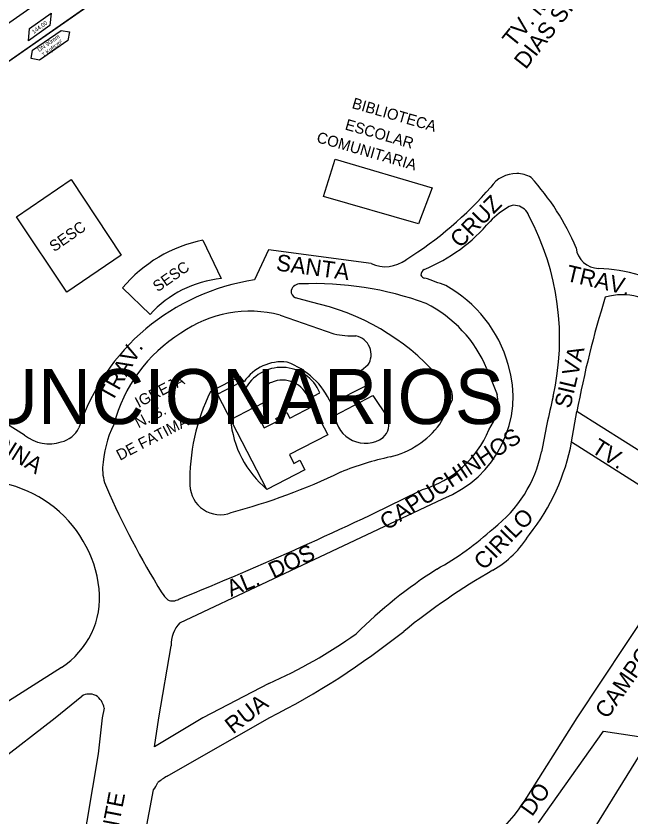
# Model space of a CAD drawing. Extents: x 325709 to 364434, y 7573432 to 7597073.
# Drawn here: x 337753.4 to 337977, y 7589465.9 to 7589757.3 of the extents above; entities that cross this region are included whole.
import ezdxf

# ---------------------------------------------------------------- set-up
doc = ezdxf.new("R2010")
doc.units = 0
for name, color, linetype in [('EDIFEXISTENT', 7, 'Continuous'), ('EDIFIDENTIF', 7, 'Continuous'), ('EDIFOBRAEXIS', 7, 'Continuous'), ('LIMITE_BAIRROS_MUNICIPIOS', 7, 'Continuous'), ('LOGRADOURO', 7, 'Continuous'), ('LOGRADOURO_TEXTO', 7, 'Continuous'), ('SIMBOLO', 7, 'Continuous'), ('TEXTO', 7, 'Continuous'), ('TUBO_PEAD_GN_90', 7, 'Continuous')]:
    doc.layers.add(name, color=color, linetype=linetype)

msp = doc.modelspace()

# ---------------------------------------------------------------- linework, layer by layer
at = {"layer": 'EDIFEXISTENT'}
for p, q in [((337865.22, 7589691.61), (337869.48, 7589705.19)), ((337869.48, 7589705.19), (337904.68, 7589694.73)), ((337753.58, 7589684.27), (337773.5, 7589697.83)), ((337773.5, 7589697.83), (337791.63, 7589670.29)), ((337904.68, 7589694.73), (337899.77, 7589681.63)), ((337899.77, 7589681.63), (337865.22, 7589691.61)), ((337771.86, 7589656.78), (337753.58, 7589684.27)), ((337821.38, 7589675.69), (337828.01, 7589661.75)), ((337791.63, 7589670.29), (337771.86, 7589656.78)), ((337802.14, 7589648.71), (337792.16, 7589658.35)), ((337826.65, 7589619.68), (337834.98, 7589624.01)), ((337834.98, 7589624.01), (337839.78, 7589614.76)), ((337859.74, 7589618.02), (337863.92, 7589620.19)), ((337844.63, 7589585.05), (337826.65, 7589619.68)), ((337839.78, 7589614.76), (337831.4, 7589610.41)), ((337839.78, 7589614.76), (337843.97, 7589616.93)), ((337839.78, 7589614.76), (337843.6, 7589607.39)), ((337852.96, 7589610.95), (337861.4, 7589615.33)), ((337861.4, 7589615.33), (337866.79, 7589604.93)), ((337847.94, 7589610.89), (337851.92, 7589612.96)), ((337851.92, 7589612.96), (337852.96, 7589610.95)), ((337843.6, 7589607.39), (337848.45, 7589609.91)), ((337848.45, 7589609.91), (337847.94, 7589610.89)), ((337866.79, 7589604.93), (337852.81, 7589597.68)), ((337852.81, 7589597.68), (337854.46, 7589594.51)), ((337854.46, 7589594.51), (337856.65, 7589595.65)), ((337856.65, 7589595.65), (337858.46, 7589592.17)), ((337858.46, 7589592.17), (337844.63, 7589585.05))]:
    msp.add_line(p, q, dxfattribs=at)
for centre, radius, start, end in [((337831.24, 7589625.78), 50.87, 101.1753, 140.1958), ((337832.18, 7589621.28), 40.68, 95.8819, 137.6058), ((337849.99, 7589614.35), 15.09, 22.7351, 152.9065), ((337848.02, 7589619.5), 4.79, 110.2139, 212.3529), ((337850.32, 7589614.89), 9.93, 18.3749, 113.5191)]:
    msp.add_arc(centre, radius, start, end, dxfattribs=at)
at = {"layer": 'EDIFOBRAEXIS'}
for p, q in [((337860.89, 7589653.12), (337855.01, 7589654.71)), ((337869.39, 7589611.91), (337883.17, 7589619.21)), ((337883.17, 7589619.21), (337888.63, 7589611.08))]:
    msp.add_line(p, q, dxfattribs=at)
msp.add_lwpolyline([(337836.34, 7589624.22), (337834.89, 7589626.07), (337824.09, 7589620.61)], dxfattribs=at)
for centre, radius, start, end in [((337856, 7589657.06), 2.54, 171.2027, 247.0167), ((337842.87, 7589569.44), 85.6, 41.776, 77.8491), ((337850.09, 7589614.83), 16.65, 83.4955, 145.648), ((337841.97, 7589604.66), 28.51, 23.989, 69.4661), ((337903.29, 7589618.24), 8.91, 357.0377, 67.4592), ((337889.76, 7589588.41), 73.14, 153.8787, 181.4576), ((337775.16, 7589683.17), 151.83, 330.6463, 334.4887), ((337880.43, 7589612.91), 11.09, 185.1891, 305.4939), ((337868.86, 7589613.82), 37.61, 185.1982, 229.8969), ((337882.53, 7589608.77), 6.52, 311.6203, 20.8159), ((337882.25, 7589627.45), 31.42, 283.2689, 323.4734), ((337913.15, 7589487.48), 111.92, 102.2204, 111.8395), ((337770.87, 7589801.87), 233.32, 285.1026, 295.5529), ((337827.64, 7589586.84), 11, 181.5218, 291.4631)]:
    msp.add_arc(centre, radius, start, end, dxfattribs=at)
at = {"layer": 'LIMITE_BAIRROS_MUNICIPIOS'}
msp.add_lwpolyline([(337471.68, 7589702.11), (337850.59, 7589885.17), (338105.97, 7589691.77), (337839.73, 7589261.51)], dxfattribs=at)
at = {"layer": 'LOGRADOURO'}
for p, q in [((337777.7, 7589773.53), (337681.39, 7589706.29)), ((337756.51, 7589604.8), (337681.39, 7589651.86)), ((337849.42, 7589648.46), (337869.03, 7589641.59)), ((337924.66, 7589628.94), (337928.42, 7589619.62)), ((337955.46, 7589602.34), (337957.37, 7589613.36)), ((337986.4, 7589595.08), (337957.37, 7589613.36)), ((337955.46, 7589602.34), (338003.49, 7589571.67)), ((337812.94, 7589536.51), (337908.56, 7589581.66)), ((338003.49, 7589571.67), (337957.37, 7589501.91)), ((337805.35, 7589501.91), (337809.76, 7589528.15)), ((337769.92, 7589520.28), (337741.14, 7589501.91)), ((337845.36, 7589514.39), (337821.3, 7589501.91)), ((337767.58, 7589501.91), (337777.32, 7589509.85)), ((337785.44, 7589505.39), (337784.7, 7589501.91)), ((337723.81, 7589467.93), (337767.58, 7589501.91)), ((337821.3, 7589501.91), (337803.75, 7589491.32)), ((337803.75, 7589491.32), (337805.35, 7589501.91)), ((337808.33, 7589480.67), (337845.48, 7589501.91)), ((337957.37, 7589501.91), (337937.57, 7589470.65)), ((337943.46, 7589463.74), (337967.01, 7589497.08)), ((337967.01, 7589497.08), (338018.98, 7589489.01)), ((337789.48, 7589402.84), (337803.39, 7589475.72))]:
    msp.add_line(p, q, dxfattribs=at)
for points in [[(337685.23, 7589695.1), (337851.99, 7589811.81), (337884.5, 7589834.2)], [(337882.51, 7589667.18), (337845.21, 7589672.2), (337840.14, 7589661.24)], [(337881.39, 7589630.23), (337879.07, 7589628.26), (337881.02, 7589622.84), (337868.02, 7589616.26)], [(337784.7, 7589501.91), (337783.28, 7589488.81), (337768.69, 7589402.37)]]:
    msp.add_lwpolyline(points, dxfattribs=at)
for centre, radius, start, end in [((337935.34, 7589688.88), 11.08, 89.0512, 146.266), ((337935.34, 7589688.88), 11.08, 61.0979, 89.0512), ((337873.38, 7589637.56), 90.86, 22.891, 42.1924), ((337821.26, 7589786.42), 139.09, 302.1242, 318.9295), ((337949.88, 7589658.82), 33.83, 120.451, 135.4175), ((337934.56, 7589684.39), 4.03, 72.6768, 116.9118), ((337934.71, 7589682.85), 5.48, 18.6993, 78.972), ((337856.47, 7589639.98), 94.62, 347.0801, 28.1464), ((337877.72, 7589723.12), 62.89, 292.5737, 319.8465), ((337965.52, 7589673.9), 8.49, 186.7436, 268.1865), ((337887.65, 7589678.58), 12.51, 245.7455, 307.2705), ((337903.27, 7589662.81), 2.64, 122.206, 175.7575), ((337963.92, 7589610.47), 54.96, 72.8158, 88.614), ((337851.71, 7589582.75), 79.34, 98.3831, 161.8912), ((337902.18, 7589663.62), 1.67, 201.4748, 267.6442), ((335802.31, 7583854.89), 6175.04, 70.045846, 70.120265), ((337856.63, 7589656.55), 3.26, 86.2667, 164.1231), ((337861.95, 7589542.05), 117.86, 69.8549, 92.4843), ((337886.57, 7589617.57), 47.62, 15.7878, 61.0052), ((338318.38, 7589545.85), 367.26, 162.7161, 169.4089), ((337973.77, 7589634.35), 21.5, 339.1906, 106.402), ((337881.07, 7589610.56), 47.31, 22.8645, 63.0012), ((337838.39, 7589606.58), 43.31, 75.2507, 125.3173), ((337843.32, 7589594.29), 56.28, 122.1803, 165.2157), ((337875.78, 7589674.02), 33.13, 258.2441, 272.1743), ((337875.52, 7589634.07), 7.01, 326.8447, 77.5092), ((337894.37, 7589618.83), 39.79, 290.9049, 17.095), ((337910.66, 7589617.04), 17.94, 324.7934, 8.285), ((338421.79, 7589509.01), 485.67, 166.9327, 169.362), ((337825.71, 7589590.88), 40.86, 154.2264, 177.0693), ((337767.73, 7589611.69), 9.58, 282.7961, 333.4544), ((337890.64, 7589620.95), 37.49, 286.4219, 337.6569), ((337765.38, 7589615.53), 13.92, 230.4184, 288.7694), ((337879.35, 7589616.62), 77.44, 321.6629, 349.3745), ((337898.98, 7589607.84), 46.39, 307.1678, 348.6039), ((337800.66, 7589592.27), 15.78, 177.4697, 204.0425), ((337739.48, 7589543.8), 44.47, 6.6074, 101.5416), ((338054.16, 7589702.31), 292.13, 203.496, 212.0127), ((337339.21, 7590716.43), 1263.35, 292.0094, 296.41538), ((337853, 7589651.75), 109.63, 299.1672, 312.46), ((337907, 7589589.18), 38.97, 300.5065, 328.1072), ((338001.46, 7589407.32), 176.47, 122.5787, 134.8219), ((338046.96, 7589345.69), 241.88, 119.7912, 129.1029), ((337753.5, 7589545.77), 30.32, 302.7886, 5.9623), ((337817.49, 7589554.32), 13, 211.92, 226.6115), ((337810.37, 7589548.72), 4.25, 244.8292, 302.7026), ((337821.98, 7589528.28), 12.22, 137.6841, 180.6185), ((337714.81, 7589758.75), 288.17, 296.9659, 308.5516), ((337770.17, 7589682.98), 184.59, 294.0355, 305.3839), ((337780.06, 7589505.07), 5.51, 65.1712, 119.7965), ((337778.88, 7589504.44), 6.63, 8.2916, 58.1486), ((337821.37, 7589457.85), 26.29, 119.7537, 128.6383), ((337795.34, 7589482.25), 10.37, 320.9733, 338.1252), ((337885.83, 7589504.8), 61.99, 288.3625, 326.5714)]:
    msp.add_arc(centre, radius, start, end, dxfattribs=at)
at = {"layer": 'SIMBOLO'}
for points in [[(337765.67, 7589753.84), (337757.89, 7589748.2), (337758.34, 7589752.69), (337766.12, 7589758.34)], [(337759.41, 7589744.82), (337769.79, 7589752.01), (337772.83, 7589751.47), (337772.83, 7589751.47), (337772.28, 7589748.42), (337761.91, 7589741.22), (337758.86, 7589741.77), (337758.86, 7589741.77)]]:
    msp.add_lwpolyline(points, close=True, dxfattribs=at)
at = {"layer": 'TUBO_PEAD_GN_90'}
msp.add_lwpolyline([(337922.76, 7589878.72), (337897.7, 7589843.27), (337685.23, 7589695.1), (337685.23, 7589695.1), (337685.23, 7589695.1), (337674.93, 7589664.99)], dxfattribs=at)

# ---------------------------------------------------------------- texts
at = {"layer": 'EDIFIDENTIF'}
for s, rotation, p in [('BIBLIOTECA', 343.9046, (337875.29, 7589723.83)), ('ESCOLAR', 343.9046, (337872.77, 7589716.05)), ('COMUNITARIA', 343.9046, (337862.43, 7589711.43)), ('SESC', 34.9809, (337767.28, 7589671.31)), ('SESC', 34.9809, (337804.92, 7589656.72)), ('IGREJA', 27.4349, (337797.97, 7589614.6)), ('N. S.', 27.4349, (337797.91, 7589607.21)), ('DE FATIMA', 27.4349, (337791.19, 7589595.43))]:
    msp.add_text(s, height=4, rotation=rotation, dxfattribs=at).set_placement(p)
at = {"layer": 'LIMITE_BAIRROS_MUNICIPIOS'}
msp.add_text('JARDIM FUNCIONARIOS', height=20, dxfattribs=at).set_placement((337618.77, 7589608.82))
at = {"layer": 'LOGRADOURO_TEXTO'}
for s, rotation, p in [('TV. MANOEL', 50.8464, (337934.44, 7589745.5)), ('DIAS SIMOES', 51.8515, (337938.76, 7589737.59)), ('CRUZ', 45.6906, (337914.93, 7589672.56)), ('SANTA', 352.3227, (337847.74, 7589664.72)), ('TRAV.', 346.7611, (337953.1, 7589660.98)), ('TRAV.', 60.7117, (337788.33, 7589616.49)), ('SILVA', 76.7262, (337954.96, 7589614.2)), ('MEDINA', 327.9356, (337734.19, 7589607)), ('CAPUCHINHOS', 33.6637, (337888.27, 7589569.92)), ('TV.', 327.4378, (337962.23, 7589598.84)), ('CIRILO', 45.9718, (337923.57, 7589555.34)), ('DOS', 25.5021, (337847.02, 7589552.46)), ('AL.', 22.5661, (337831.55, 7589545.9)), ('CAMPO', 54.9465, (337968.41, 7589501.21)), ('RUA', 37.9724, (337832.32, 7589495.83)), ('DO', 54.2782, (337941.05, 7589465.73)), ('AMARANTE', 79.0225, (337784.64, 7589430.49))]:
    msp.add_text(s, height=6, rotation=rotation, dxfattribs=at).set_placement(p)
at = {"layer": 'TEXTO'}
for s, rotation, p in [('144,00', 35.9612, (337759.86, 7589750.72)), ('DN 90mm', 34.7684, (337761.83, 7589744.13)), ('7 Kgf/cm²', 37.3231, (337763.5, 7589742.27))]:
    msp.add_text(s, height=1.5, rotation=rotation, dxfattribs=at).set_placement(p)

doc.saveas('drawing.dxf')
